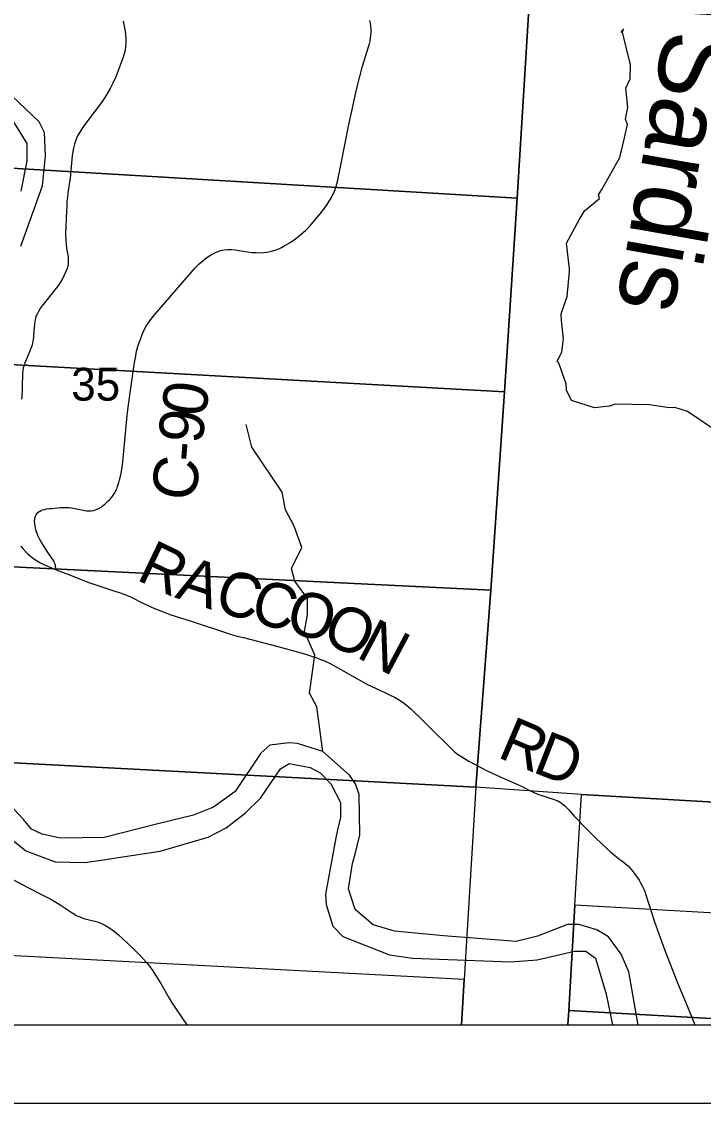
# Model space of a CAD drawing. Extents: x 21.4 to 65.3, y 4 to 26.
# Drawn here: x 26.662 to 27.53, y 17.954 to 19.331 of the extents above; entities that cross this region are included whole.
import ezdxf

# ---------------------------------------------------------------- set-up
doc = ezdxf.new("R2010")
doc.units = 0
for name, color, linetype in [('Default', 7, 'Continuous'), ('GM_X_County_Road', 7, 'Continuous'), ('GM_X_County_Road_Text', 7, 'Continuous'), ('GM_X_Major_River', 7, 'Continuous'), ('GM_X_Minor_River', 7, 'Continuous'), ('GM_X_Minor_River_Text', 7, 'Continuous'), ('GM_X_Section', 7, 'Continuous'), ('GM_X_Section_Text', 7, 'Continuous'), ('SH_Cut_Line', 7, 'Continuous'), ('SH_Data', 7, 'Continuous')]:
    doc.layers.add(name, color=color, linetype=linetype)

msp = doc.modelspace()

# ---------------------------------------------------------------- linework, layer by layer
at = {"layer": 'Default'}
for points in [[(27.2217, 18.0542), (27.3572, 18.0542), (27.3583, 18.0722), (27.3661, 18.2064), (27.3744, 18.3474), (27.2401, 18.3567), (27.2253, 18.1117)], [(27.6828, 18.0542), (28.255, 18.0542), (28.2609, 18.1555), (27.3661, 18.2064), (27.3583, 18.0722)], [(26.1864, 18.0542), (27.2217, 18.0542), (27.2253, 18.1117), (26.1936, 18.1661)], [(27.3572, 18.0542), (27.6828, 18.0542), (27.3583, 18.0722)]]:
    msp.add_lwpolyline(points, close=True, dxfattribs=at)
msp.add_lwpolyline([(25.1151, 18.0542), (28.6177, 18.0542)], dxfattribs=at)
at = {"layer": 'GM_X_County_Road'}
for points in [[(26.7909, 19.3317), (26.7927, 19.3232), (26.7934, 19.3191), (26.7941, 19.3148), (26.7945, 19.3091), (26.7945, 19.3041), (26.7941, 19.2992), (26.7934, 19.2947), (26.7923, 19.2903), (26.7911, 19.2861), (26.7895, 19.2812), (26.7815, 19.261), (26.7777, 19.2527), (26.7743, 19.246), (26.7696, 19.2378), (26.7646, 19.2301), (26.7433, 19.202), (26.7392, 19.196), (26.7358, 19.1905), (26.7331, 19.1856), (26.7306, 19.1802), (26.729, 19.1754), (26.7277, 19.1699), (26.7269, 19.1654), (26.7263, 19.1606), (26.7234, 19.1319), (26.7207, 19.1134), (26.72, 19.1072), (26.7195, 19.1023), (26.7191, 19.0962), (26.7188, 19.0902), (26.7178, 19.0608), (26.718, 19.0534), (26.7184, 19.0473), (26.719, 19.0428), (26.7198, 19.0381), (26.7208, 19.0324), (26.721, 19.0296), (26.7212, 19.0273), (26.7212, 19.0247), (26.721, 19.0221), (26.7206, 19.0196), (26.7199, 19.0171), (26.7182, 19.0129), (26.7161, 19.0083), (26.7137, 19.0038), (26.7108, 18.9993), (26.7073, 18.9942), (26.686, 18.9668), (26.6831, 18.9621), (26.6818, 18.9598), (26.6809, 18.9578), (26.68, 18.9556), (26.6793, 18.9532), (26.6786, 18.9497), (26.6781, 18.9457), (26.6775, 18.9379), (26.6767, 18.9298), (26.6763, 18.9261), (26.6758, 18.9227), (26.6751, 18.9195), (26.674, 18.9164), (26.6726, 18.9129), (26.6696, 18.9059), (26.6675, 18.9006), (26.666, 18.897), (26.6649, 18.8936), (26.6639, 18.8903), (26.6633, 18.887), (26.6629, 18.8831), (26.6627, 18.879), (26.6625, 18.8699), (26.6624, 18.8609), (26.6622, 18.8567), (26.6619, 18.8535), (26.6614, 18.8507)], [(26.7057, 18.6334), (26.705, 18.6377), (26.7047, 18.6393), (26.7044, 18.6407), (26.7038, 18.6423), (26.7031, 18.6438), (26.7022, 18.6452), (26.6956, 18.6549), (26.6868, 18.669), (26.6849, 18.672), (26.6836, 18.6746), (26.6825, 18.677), (26.6814, 18.6795), (26.6806, 18.6818), (26.6799, 18.6843), (26.6793, 18.6866), (26.6789, 18.6892), (26.6785, 18.6923), (26.6783, 18.6952), (26.6784, 18.6972), (26.6786, 18.6989), (26.6789, 18.7002), (26.6795, 18.7018), (26.6803, 18.7034), (26.6813, 18.7048), (26.6826, 18.7062), (26.6841, 18.7074), (26.6853, 18.7081), (26.6866, 18.7088), (26.6885, 18.7096), (26.6909, 18.7103), (26.6934, 18.7108), (26.6968, 18.7113), (26.7003, 18.7116), (26.7114, 18.7125), (26.7154, 18.7127), (26.7185, 18.7127), (26.7218, 18.7125), (26.7254, 18.7121), (26.7293, 18.7115), (26.7334, 18.7107), (26.7384, 18.7096), (26.7416, 18.709), (26.7447, 18.7086), (26.7477, 18.7084), (26.7502, 18.7085), (26.7531, 18.709), (26.7556, 18.7097), (26.7579, 18.7106), (26.7606, 18.7119), (26.7629, 18.7133), (26.7645, 18.7145), (26.766, 18.7157), (26.7675, 18.7168), (26.7695, 18.7186), (26.7715, 18.7206), (26.7743, 18.7234), (26.7765, 18.7259), (26.7782, 18.7282), (26.7799, 18.7307), (26.7813, 18.7331), (26.7823, 18.7353), (26.7833, 18.7376), (26.784, 18.7396), (26.7848, 18.7419), (26.7856, 18.7446), (26.7865, 18.7481), (26.7876, 18.7525), (26.7884, 18.7566), (26.7893, 18.7616), (26.7897, 18.7644), (26.7901, 18.7675), (26.7905, 18.7708), (26.7962, 18.8298), (26.7966, 18.8334), (26.7969, 18.8366), (26.7975, 18.8405), (26.8052, 18.8946), (26.8063, 18.9015), (26.807, 18.9056), (26.8076, 18.9089), (26.8082, 18.9116), (26.809, 18.9146), (26.8099, 18.9176), (26.8111, 18.9215), (26.8125, 18.9255), (26.8138, 18.9293), (26.8151, 18.9328), (26.8164, 18.936), (26.8182, 18.9397), (26.8205, 18.9436), (26.8227, 18.9472), (26.825, 18.9505), (26.8279, 18.9542), (26.8314, 18.9583), (26.8777, 19.0119), (26.8828, 19.0177), (26.8878, 19.0228), (26.8929, 19.0273), (26.8977, 19.031), (26.9024, 19.034), (26.9078, 19.0369), (26.9128, 19.0391), (26.9163, 19.0402), (26.9198, 19.0409), (26.924, 19.0413), (26.9283, 19.0413), (26.9338, 19.0408), (26.9493, 19.0382), (26.9548, 19.0375), (26.9603, 19.0371), (26.9652, 19.037), (26.97, 19.0373), (26.9745, 19.0378), (26.9798, 19.0388), (26.9846, 19.0403), (26.9891, 19.042), (26.9925, 19.0436), (26.9969, 19.046), (27.0038, 19.0502), (27.0104, 19.0548), (27.0177, 19.0606), (27.0233, 19.0655), (27.0281, 19.0702), (27.0331, 19.0758), (27.0439, 19.0891), (27.0508, 19.0986), (27.0532, 19.1025), (27.0556, 19.1066), (27.0577, 19.1104), (27.0595, 19.114), (27.0609, 19.1177), (27.0621, 19.1214), (27.0631, 19.1249), (27.0638, 19.1278), (27.0685, 19.1506), (27.0779, 19.198), (27.0885, 19.2463), (27.0957, 19.2744), (27.1033, 19.2989), (27.1045, 19.3031), (27.1053, 19.3065), (27.106, 19.3102), (27.1064, 19.3139), (27.1066, 19.3175), (27.1068, 19.3212), (27.1065, 19.3253), (27.1059, 19.3291), (27.1051, 19.3327)], [(26.6609, 18.6636), (26.6634, 18.6605), (26.6668, 18.6567), (26.6698, 18.6539), (26.6732, 18.6508), (26.6773, 18.6475), (26.6814, 18.6447), (26.6857, 18.6424), (26.6902, 18.6402), (26.697, 18.6372), (26.7057, 18.6334), (26.7226, 18.6268), (26.7473, 18.6171), (26.7818, 18.6058), (26.7864, 18.6043), (26.7906, 18.6028), (26.7952, 18.601), (26.8004, 18.5988), (26.8061, 18.5961), (26.8127, 18.5927), (26.8252, 18.5867), (26.8309, 18.5843), (26.8369, 18.5818), (26.8504, 18.5766), (26.8574, 18.5742), (26.8638, 18.5722), (26.8721, 18.5697), (26.8788, 18.5677), (26.9238, 18.5528), (26.9302, 18.5508), (26.9363, 18.5491), (26.9443, 18.547), (26.9881, 18.5357), (27.0159, 18.528), (27.0233, 18.5258), (27.0306, 18.5234), (27.0376, 18.5211), (27.0424, 18.5193), (27.0464, 18.5178), (27.0499, 18.5163), (27.0537, 18.5145), (27.0573, 18.5126), (27.062, 18.5098), (27.1014, 18.488), (27.1186, 18.4796), (27.124, 18.4772), (27.1302, 18.4744), (27.1363, 18.4713), (27.1417, 18.4681), (27.1474, 18.4643), (27.1518, 18.4609), (27.1547, 18.4585), (27.1575, 18.456), (27.1615, 18.4522), (27.1675, 18.4467), (27.1854, 18.4286), (27.2037, 18.4105), (27.2085, 18.4058), (27.213, 18.4018), (27.2168, 18.3988), (27.2208, 18.3961), (27.2255, 18.393), (27.2311, 18.3896), (27.2551, 18.3772), (27.2747, 18.368), (27.2952, 18.3592), (27.2988, 18.3575), (27.3026, 18.3555), (27.312, 18.3506), (27.3145, 18.3495), (27.3171, 18.3485), (27.3198, 18.3474), (27.3225, 18.3465), (27.3304, 18.344), (27.3396, 18.341), (27.342, 18.3403), (27.3444, 18.3393), (27.3466, 18.3381), (27.3487, 18.3367), (27.3508, 18.335), (27.3532, 18.3329), (27.3556, 18.3304), (27.3582, 18.3277), (27.3606, 18.3252), (27.3654, 18.3195), (27.3821, 18.3023), (27.3921, 18.2921), (27.407, 18.2781), (27.4113, 18.2743), (27.417, 18.2696), (27.4233, 18.2648), (27.4269, 18.2621), (27.4305, 18.2592), (27.4337, 18.2564), (27.4362, 18.2538), (27.4383, 18.2514), (27.4404, 18.2489), (27.4457, 18.2413), (27.4477, 18.2381), (27.4496, 18.2349), (27.4511, 18.2321), (27.4526, 18.2294), (27.4537, 18.2268), (27.455, 18.2237), (27.4563, 18.2198), (27.4674, 18.1852), (27.4803, 18.1502), (27.4968, 18.1074), (27.5111, 18.0731), (27.5189, 18.0542)], [(26.6442, 18.2424), (26.6618, 18.2331), (26.6729, 18.2274), (26.6872, 18.22), (26.6988, 18.2141), (26.7052, 18.2104), (26.711, 18.2069), (26.7146, 18.2045), (26.7197, 18.201), (26.7247, 18.1974), (26.7315, 18.1932), (26.7365, 18.191), (26.7424, 18.1891), (26.755, 18.186), (26.7603, 18.1845), (26.7643, 18.1829), (26.7676, 18.1812), (26.7729, 18.178), (26.7799, 18.173), (26.7852, 18.1687), (26.7907, 18.1637), (26.7971, 18.1578), (26.8052, 18.15), (26.8125, 18.1424), (26.8167, 18.1379), (26.8231, 18.1303), (26.8287, 18.1228), (26.8345, 18.114), (26.839, 18.1066), (26.8495, 18.0882), (26.8527, 18.0829), (26.856, 18.0777), (26.8674, 18.0607), (26.8719, 18.0542)]]:
    msp.add_lwpolyline(points, dxfattribs=at)
at = {"layer": 'GM_X_Major_River'}
for points in [[(26.6606, 19.0452), (26.6885, 19.1223), (26.6921, 19.1603), (26.6908, 19.1899), (26.6839, 19.2035), (26.6493, 19.2367)], [(26.6518, 19.2029), (26.6686, 19.1761), (26.6683, 19.1541), (26.6609, 19.1154)], [(27.1365, 18.1732), (27.1093, 18.1813), (27.0865, 18.2009), (27.078, 18.2271), (27.0831, 18.2593), (27.0865, 18.2715), (27.0924, 18.2962), (27.0914, 18.3474), (27.0867, 18.361), (27.0791, 18.372), (27.0453, 18.4021), (27.0131, 18.4122), (27.0025, 18.4129), (26.9779, 18.4101), (26.9663, 18.4001), (26.9336, 18.351), (26.9061, 18.3311), (26.8805, 18.3211), (26.8336, 18.3095), (26.7668, 18.2928), (26.7112, 18.2917), (26.6877, 18.2968), (26.6744, 18.3032), (26.6642, 18.3157), (26.652, 18.3285)], [(26.6446, 18.2939), (26.667, 18.2755), (26.7045, 18.2617), (26.7424, 18.2607), (26.7631, 18.2639), (26.779, 18.2663), (26.838, 18.2753), (26.8991, 18.2932), (26.9222, 18.3047), (26.9466, 18.3242), (26.9658, 18.3425), (26.9913, 18.3798), (27.0023, 18.3867), (27.0291, 18.3819), (27.042, 18.3748), (27.0553, 18.3608), (27.0676, 18.337), (27.0677, 18.318), (27.064, 18.3025), (27.0618, 18.2922), (27.0485, 18.2204), (27.0494, 18.2075), (27.0578, 18.1799), (27.0708, 18.1667), (27.1299, 18.1431), (27.1594, 18.1388), (27.2843, 18.1342)], [(27.4467, 18.0542), (27.4348, 18.1218), (27.4249, 18.1441), (27.4089, 18.166), (27.3941, 18.175), (27.371, 18.1817), (27.3566, 18.1817), (27.3185, 18.167), (27.2913, 18.16), (27.1986, 18.1674), (27.1365, 18.1732)], [(27.2843, 18.1342), (27.3179, 18.137), (27.3655, 18.1479), (27.3799, 18.148), (27.3924, 18.139), (27.4059, 18.0932), (27.4141, 18.0542)]]:
    msp.add_lwpolyline(points, dxfattribs=at)
at = {"layer": 'GM_X_Minor_River'}
for points in [[(27.5395, 18.8144), (27.5092, 18.8348), (27.4934, 18.8401), (27.4869, 18.8394), (27.4835, 18.8401), (27.4612, 18.8435), (27.4174, 18.8441), (27.4102, 18.8418), (27.3909, 18.8395), (27.3618, 18.849), (27.3554, 18.8619), (27.355, 18.8702), (27.3455, 18.8964), (27.3436, 18.8987), (27.3496, 18.9109), (27.3515, 18.9276), (27.3492, 18.9508), (27.3485, 18.9591), (27.3564, 18.9812), (27.359, 19.0131), (27.3594, 19.0166), (27.3552, 19.0492), (27.3714, 19.0789), (27.3782, 19.0904), (27.3975, 19.106), (27.3963, 19.1105), (27.4005, 19.1174), (27.4231, 19.1581), (27.4292, 19.1832), (27.4329, 19.2003), (27.4303, 19.2072), (27.4333, 19.222), (27.431, 19.2467), (27.4366, 19.2585), (27.437, 19.2767), (27.4362, 19.2794), (27.4268, 19.3178), (27.4279, 19.3219), (27.4245, 19.3174)], [(27.0453, 18.4021), (27.0375, 18.4591), (27.0282, 18.4765), (27.035, 18.5245), (27.0219, 18.5549), (27.0256, 18.5764), (27.0255, 18.5969), (27.0095, 18.6191), (27.0055, 18.6352), (27.0184, 18.6617), (27.0086, 18.689), (26.9975, 18.7099), (26.9933, 18.7324), (26.955, 18.7894), (26.9475, 18.8185)]]:
    msp.add_lwpolyline(points, dxfattribs=at)
at = {"layer": 'GM_X_Section'}
for points in [[(26.2711, 19.4096), (27.3079, 19.3538), (27.2925, 19.1065), (26.2556, 19.168), (26.2708, 19.4063)], [(27.5403, 19.3404), (28.3017, 19.2998), (28.3345, 19.2762), (28.3347, 19.276), (28.3387, 19.2192), (28.3305, 19.1915), (28.269, 18.2956), (27.3744, 18.3474), (27.2401, 18.3567), (27.2592, 18.6074), (27.2763, 18.86), (27.2925, 19.1065), (27.3079, 19.3538)], [(27.2925, 19.1065), (27.2763, 18.86), (26.2403, 18.9172), (26.2556, 19.168)], [(26.2403, 18.9172), (27.2763, 18.86), (27.2592, 18.6074), (26.2238, 18.6579)], [(27.2592, 18.6074), (27.2401, 18.3567), (26.208, 18.4108), (26.2238, 18.6579)], [(27.2401, 18.3567), (27.2253, 18.1117), (26.1936, 18.1661), (26.208, 18.4108)], [(27.3744, 18.3474), (28.269, 18.2956), (28.2609, 18.1555), (27.3661, 18.2064)]]:
    msp.add_lwpolyline(points, close=True, dxfattribs=at)
at = {"layer": 'SH_Cut_Line'}
msp.add_lwpolyline([(23.5473, 18.0542), (28.6177, 18.0542)], dxfattribs=at)
at = {"layer": 'SH_Data'}
for p, q in [((23.5473, 18.0542), (30.3473, 18.0542)), ((23.4473, 17.9542), (30.4473, 17.9542))]:
    msp.add_line(p, q, dxfattribs=at)

# ---------------------------------------------------------------- texts
at = {"layer": 'GM_X_County_Road_Text'}
for s, rotation, p in [('0', 81.9542, (26.8956, 18.8268)), ('9', 83.35, (26.8916, 18.7924)), ('-', 85.3252, (26.8897, 18.7697)), ('C', 80.4007, (26.8813, 18.7184)), ('R', 334.3985, (26.8062, 18.6215)), ('A', 341.6318, (26.8556, 18.5984)), ('C', 343.3917, (26.9049, 18.5821)), ('C', 344.3882, (26.9506, 18.5685)), ('O', 344.246, (26.9955, 18.5559)), ('O', 335.6429, (27.0415, 18.5431)), ('N', 332.0469, (27.0862, 18.5229)), ('R', 336.9157, (27.2658, 18.3955)), ('D', 338.667, (27.3105, 18.3765))]:
    msp.add_text(s, height=0.0568, rotation=rotation, dxfattribs=at).set_placement(p)
at = {"layer": 'GM_X_Minor_River_Text'}
msp.add_text('Sardis', height=0.0947, rotation=259.9987, dxfattribs=at).set_placement((27.4813, 19.3234))
at = {"layer": 'GM_X_Section_Text'}
msp.add_text('35', height=0.04186, rotation=0, dxfattribs=at).set_placement((26.7249, 18.8487))

doc.saveas('drawing.dxf')
